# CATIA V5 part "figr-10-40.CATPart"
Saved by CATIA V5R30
Part number: Part3
Bounding box of the stored display mesh (mm): x -57.458 to 20, y -85.932 to 127.979, z -59.826 to 86.386
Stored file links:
  D:\PROJECTS\CATIA V56R 2020\Resources\Parts File\c10_catia_v5_6r2020_prt\figr-10-40.CATPart
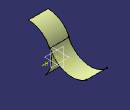
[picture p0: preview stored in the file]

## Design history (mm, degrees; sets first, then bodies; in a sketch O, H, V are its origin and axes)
Body1 (main body)
  Sketch1 on yz-plane, origin (0, 0, 0), H (0, 1, 0), V (0, 0, 1)
    arc A1 centre (-86.3872, 0) radius 86.3872 from (-24.0683, -59.8256) to (-85.9323, 86.386) ccw
    point P1 (-86.3872, 0)
    coincidence: A1 O, P1 H
  Extrude1: Element1 Sketch1, Lim1 20, Lim2 53
  Sketch2 on zx-plane, origin (0, 0, 0), H (-1, 0, 0), V (0, 0, 1)
    line L1 (-18.8028, 37.5161) -> (51.5353, 37.5161)
    horizontal: L1 H
  Project1: ToProject Sketch2, Support Extrude1
  Sketch3 on xy-plane, origin (0, 0, 0), H (1, 0, 0), V (0, 1, 0)
    line L1 (-57.4576, 127.9794) -> (17.5097, 127.9794)
    horizontal: L1 H
  Sweep1: type Circle, Guide (Project1; Sketch3), Reference Extrude1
